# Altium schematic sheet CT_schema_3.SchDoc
size 288 x 169 mm
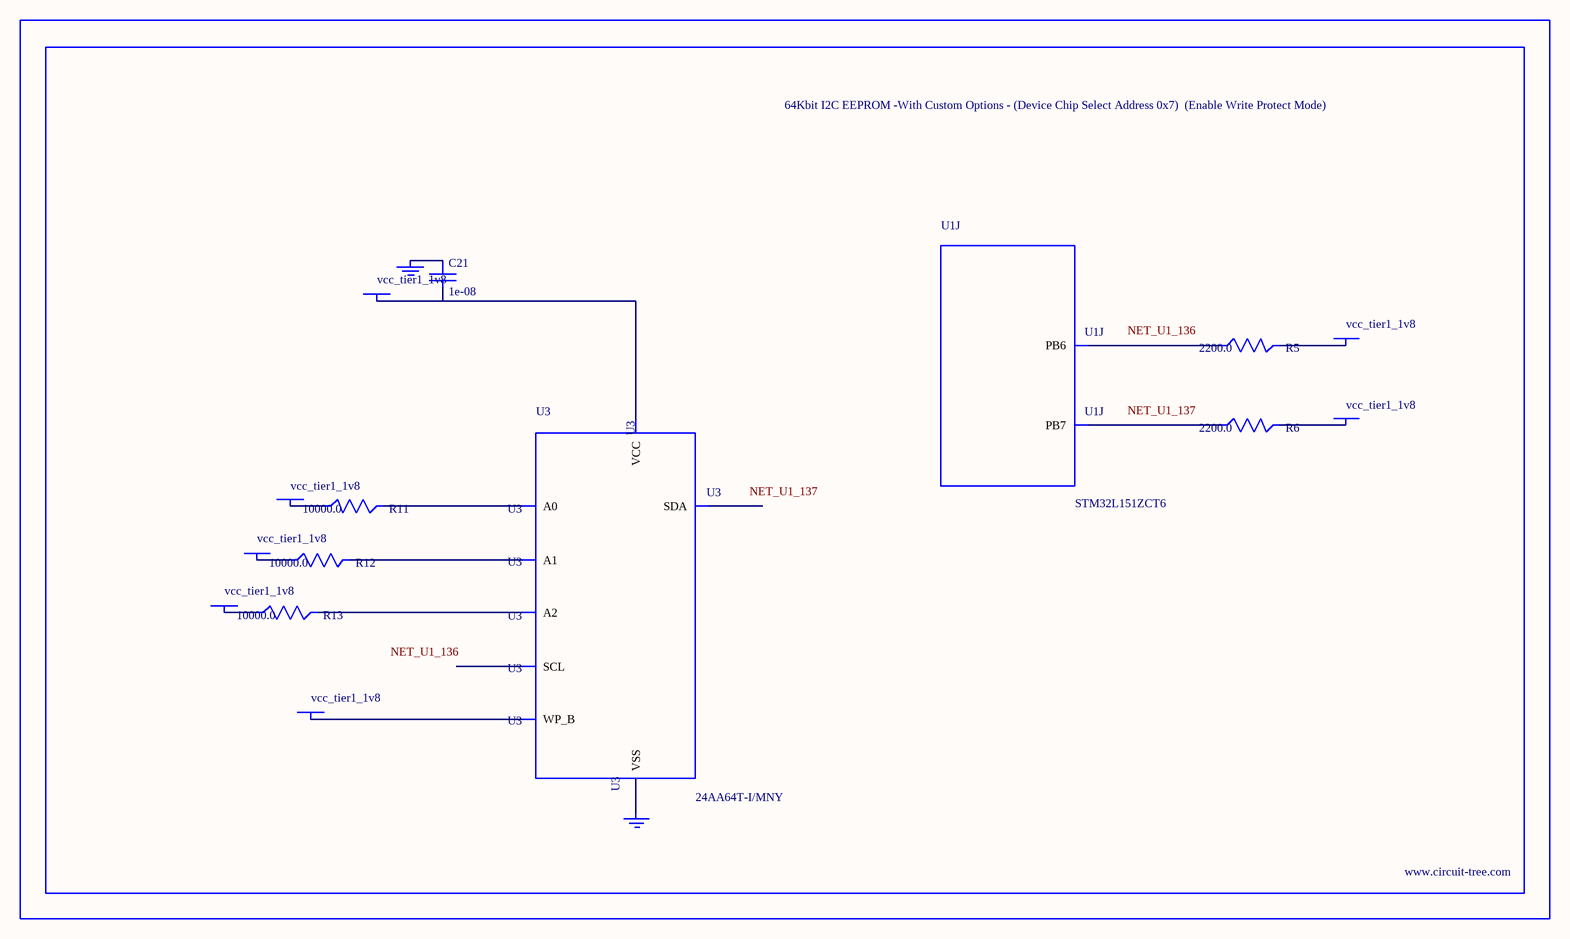
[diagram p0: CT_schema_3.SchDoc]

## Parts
BORDER2  (no value)
C21  1e-08  [C0402]
GND_INSTANCE_2_0  (no value)
GND_INSTANCE_2_1  (no value)
POWER_INSTANCE_2_0  vcc_tier1_1v8
POWER_INSTANCE_2_1  vcc_tier1_1v8
POWER_INSTANCE_2_2  vcc_tier1_1v8
POWER_INSTANCE_2_3  vcc_tier1_1v8
POWER_INSTANCE_2_4  vcc_tier1_1v8
POWER_INSTANCE_2_5  vcc_tier1_1v8
POWER_INSTANCE_2_6  vcc_tier1_1v8
R5  2200.0  [R0603]
R6  2200.0  [R0603]
R11  10000.0  [R0603]
R12  10000.0  [R0603]
R13  10000.0  [R0603]
U1  STM32L151ZCT6  [LQFP144]  (part J of 11)
U3  24AA64T-I/MNY  [TDFN-8/6MM]

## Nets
NetC21_1: C21.1 GND_INSTANCE_2_0.0(GND)
NetC21_2: C21.2 POWER_INSTANCE_2_4.0(PWR) U3.8(VCC)
NetGND_INSTANCE_2_1_0: GND_INSTANCE_2_1.0(GND) U3.4(VSS)
NetPOWER_INSTANCE_2_0_0: POWER_INSTANCE_2_0.0(PWR) R11.1
NetPOWER_INSTANCE_2_1_0: POWER_INSTANCE_2_1.0(PWR) R12.1
NetPOWER_INSTANCE_2_2_0: POWER_INSTANCE_2_2.0(PWR) R13.1
NetPOWER_INSTANCE_2_3_0: POWER_INSTANCE_2_3.0(PWR) U3.7(WP_B)
NetPOWER_INSTANCE_2_5_0: POWER_INSTANCE_2_5.0(PWR) R5.2
NetPOWER_INSTANCE_2_6_0: POWER_INSTANCE_2_6.0(PWR) R6.2
NetR5_1: R5.1 U1.136(PB6)
NetR6_1: R6.1 U1.137(PB7)
NetR11_2: R11.2 U3.1(A0)
NetR12_2: R12.2 U3.2(A1)
NetR13_2: R13.2 U3.3(A2)

Not connected (* = marked no-connect by the designer): U3 5(SDA) 6(SCL)

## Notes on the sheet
- Labels drawn without touching a wire or pin: NET_U1_136, NET_U1_137

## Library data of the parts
BORDER2 = BORDER_PAGE2
C21 = C0402C103K3RAC
GND_INSTANCE_2_0 GND_INSTANCE_2_1 = GND
POWER_INSTANCE_2_0-POWER_INSTANCE_2_6 = PWR
R5 R6 = RC0603JR-072K2L
R11-R13 = RC0603JR-0710KL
